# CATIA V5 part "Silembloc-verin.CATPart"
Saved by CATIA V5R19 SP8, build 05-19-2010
Part number: Silemblocs-verin
Nomenclature: 61
Bounding box of the stored display mesh (mm): x -12 to 12, y -10 to 10, z -10.35 to 16.65
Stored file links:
  C:\Users\rphgr\Desktop\0_Tapis_TC520B_vitesse\Silembloc-verin.CATPart
  D:\Documents\1_Travail\1 - ac-limoges.fr\ac-limoges.fr\Emmanuel Maynard - STI2D_Turgot\3 - Supports\Tapis de course TC520B\Tapis de course TC520B_Ca\0_Tapis_TC520B.CATProduct
  D:\Documents\1_Travail\1 - ac-limoges.fr\ac-limoges.fr\Emmanuel Maynard - STI2D_Turgot\3 - Supports\Tapis de course TC520B\Tapis de course TC520B_Ca\Platine Boitier transmission vis.CATPart
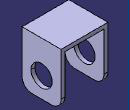
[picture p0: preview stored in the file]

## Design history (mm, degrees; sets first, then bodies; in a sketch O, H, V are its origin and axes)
Set1
  DatumSurface1
  DatumCurve1
Body1 (main body)
  AxisSystem1: origin (0, 0, 0), X (1, 0, 0), Y (0, 1, 0), Z (0, 0, 1)
  Sketch1 on ZX plane of AxisSystem1, origin (0, 0, 0), H (0, 0, 1), V (1, 0, 0)
    line L1 (-10.35, 10) -> (14.65, 10)
    line L2 (14.65, 10) -> (14.65, -10)
    line L3 (14.65, -10) -> (-10.35, -10)
    point P4 (-10.35, -10)
    reference intersected line E1 through (0, 0) direction (-1, 0) from YZ plane of AxisSystem1
    reference intersected line E2 through (0, -10) direction (-1, 0) from face of DatumSurface1
    reference projected line E3 through (0, 0) direction (0, 1) from edge of DatumCurve1
    distance P4 L2 = 25
    distance P4 E3 = 10.35
    length L1 = 25 {= Sketch1.distance(P4 L2)}
    horizontal: L1 H, L3 H
    vertical: L2 V
    symmetry: L3 L1 E1
    coincidence: L3 E2
  Pad1: profile Sketch1, direction (0, 1, 0), length 10, mirrored extent, thin wall 0, second thickness 2
  Fillet1: radius 5, on edge [start face of Pad1 | face of Pad1] (x2); edge [face of Pad1 | end face of Pad1] (x2)
  Sketch2 on face of Pad1, origin (-12, 0, 0), H (0, -1, 0), V (0, 0, 1)
    circle A1 centre (0, 0) radius 5.4
    radius A1 = 5.4
  Pocket1: profile Sketch2, direction (1, 0, 0), through (limit type 3)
